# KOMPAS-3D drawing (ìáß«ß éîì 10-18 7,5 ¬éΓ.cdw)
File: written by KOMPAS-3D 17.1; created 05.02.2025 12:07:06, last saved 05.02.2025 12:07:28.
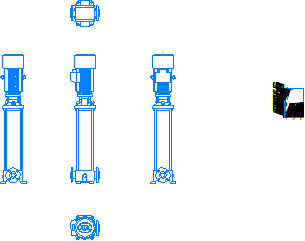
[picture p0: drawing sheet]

Sheet 1: A4, portrait

Title block, sheet 1: name: Насос ВМН 10-18 / 7,5 кВт; designation: Насос ВМН 10-18 7,5 кВт; material: Сталь 10  ГОСТ 1050-2013; mass: 255,37; sheets: 1; sheet format: A4; stored path: \\adlc.lan\data\АДЛ_ПКД\3D-модели\ADL production\Насосы ГРАНПАМП\Насосы ВМН\ВМН10\KOMPAS 3D\Насос ВМН 10-18 7,5 кВт.cdw

Views: Проекционный вид 2, Проекционный вид 3, Проекционный вид 4, Проекционный вид 5
Referenced files in \\adlc.lan\data\АДЛ_ПКД\3D-модели\ADL production\Насосы ГРАНПАМП\Насосы ВМН\ВМН10\KOMPAS 3D\: Насос ВМН 10-18 7,5 кВт.m3d
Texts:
  Andrey
  АДЛ
Dimensions and other numbers on the sheet: 1:1; 1; 7,5 кВт; 255,37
